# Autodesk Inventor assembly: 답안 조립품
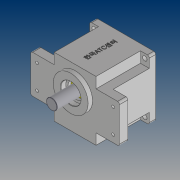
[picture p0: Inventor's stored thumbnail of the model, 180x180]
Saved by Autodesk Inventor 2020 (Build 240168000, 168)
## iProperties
Created: 2020-07
Part Number: 답안 조립품
Document SubType Name: Assembly
Designer: PC312-
Author: PC312-
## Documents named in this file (6)
- C:\Users\PC312-\Desktop\700718V1004\답안 조립품.iam
- C:\Users\PC312-\Desktop\700718V1004\본체.ipt
- C:\Users\PC312-\Desktop\700718V1004\커버.ipt
- C:\Users\PC312-\Desktop\700718V1004\베어링 608.ipt
- C:\Users\PC312-\Desktop\700718V1004\서브 축.ipt
- C:\Users\PC312-\Desktop\700718V1004\베어링 6003.ipt
